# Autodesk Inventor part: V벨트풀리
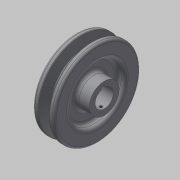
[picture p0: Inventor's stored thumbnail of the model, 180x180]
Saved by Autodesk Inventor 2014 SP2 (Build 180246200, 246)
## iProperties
Created: 2015-11
Part Number: V벨트풀리
Material: 강철, 탄소
Document SubType Name: Modeling
Designer: mduedu
Density: 1 g/cm^3
Appearance: 기본값
Author: mduedu
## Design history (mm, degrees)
sketch "스케치1"
  geometry: L1 (-9.5, 0)-(9.5, 0); L2 (0, 0)-(0, 37.7); L3 (-4.825, 37.7)-(-9.5, 37.7); L4 (-9.5, 37.7)-(-9.5, 0); L5 (0, 28.7)-(-2.074, 28.7); L6 (-2.074, 28.7)-(-4.825, 37.7); L7 (4.825, 37.7)-(9.5, 37.7); L8 (9.5, 37.7)-(9.5, 0); L9 (0, 28.7)-(2.074, 28.7); L10 (2.074, 28.7)-(4.825, 37.7); L11 (-9.5, 35)-(9.5, 35); 3 further points
  constraints: 22 end point, 7 point on line, 4 perpendicular, 3 symmetric about line, 1 coincident, 1 horizontal, 1 horizontal alignment, 1 midpoint, 1 vertical
  dimensions: "d0" = 19 distance of L1.start L1.end; "d2" = 75.4 diameter of L2.end L1 (derived); "d3" = 34 deg angle of L10 L6; "d4" = 6.3 distance between parallel lines of L11 L9; "d5" = 2.7 distance between parallel lines of L7 L11; "d6" = 8 distance of point (4, 35) point (-4, 35); "d7" = 70 diameter of L11 L1
revolve "회전1" sketch "스케치1" stored, may be unused: angle "d8" = 90 deg
sketch "스케치2"
  geometry: C1 r 24 at (0, 0); C2 r 13 at (0, 0); 1 further point
  constraints: 2 centre point, 2 coincident
  dimensions: "d9" = 48 diameter of C1; "d10" = 26 diameter of C2
extrude "돌출1" cut sketch "스케치2" distance "d11" = 6; taper "d12" = 0 deg
extrude "돌출3" join sketch "스케치2" distance "d37" = 6; taper "d38" = 0 deg
fillet "모깎기1" dims "d13" = 3
fillet "모깎기2" dims "d14" = 3
fillet "모깎기3" dims "d15" = 1, "d16" = 0.5, "d17" = 2
hole "구멍1" diameter "d20" = 16; stored, may be unused: countersink angle "d24" = 90 deg, drill point angle "d26" = 118 deg; dims "d21" = 6, "d22" = 4, "d23" = 2, "d25" = 8, "d53" = 10, "d54" = 10
sketch "스케치3"
  geometry: L1 (-2.5, 0)-(2.5, 0); L2 (2.5, 0)-(2.5, 10.3); L3 (2.5, 10.3)-(-2.5, 10.3); L4 (-2.5, 10.3)-(-2.5, 0); 2 further points
  constraints: 8 end point, 2 parallel, 1 coincident, 1 horizontal, 1 midpoint, 1 perpendicular
  dimensions: "d27" = 5 distance of L2.end L3.end; "d29" = 10.3 distance of L3.end L1.start
extrude "돌출2" cut sketch "스케치3" stored distance "d30" = 6; taper "d31" = 0 deg
chamfer "모따기1" distance "d32" = 1; stored, may be unused: second distance "d33" = 2, angle "d34" = 45 deg
node "작업 평면1"
sketch "스케치4"
  geometry: L1 (19, -27)-(19, 27) reference; 2 further points
  constraints: 1 horizontal alignment
  dimensions: "d52" = 22 distance from line of L1 point (-3, 0)
hole "구멍2" sketch "스케치4" at (-3, 0) diameter "d42" = 2.459; stored, may be unused: countersink angle "d46" = 90 deg, drill point angle "d48" = 118 deg; dims "d43" = 6, "d44" = 4, "d45" = 2, "d47" = 8
node "솔리드1"
mirror "대칭1"
